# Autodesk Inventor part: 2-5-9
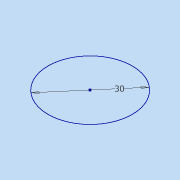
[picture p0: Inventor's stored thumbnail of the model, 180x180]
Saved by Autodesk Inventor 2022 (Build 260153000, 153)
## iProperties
Created: 2021-07
Part Number: 2-5-9
Material: 一般
Document SubType Name: Modeling
Designer: DesignLab
Density: 1 g/cm^3
Appearance: 既定
Author: DesignLab
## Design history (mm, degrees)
sketch "スケッチ1"
  geometry: C1 r 15 at (0, 0); 1 further point
  constraints: 1 centre point, 1 coincident
  dimensions: "d0" = 30 dimension on point (0, 0) C1.centre C1; "d0" = 30 diameter of C1
